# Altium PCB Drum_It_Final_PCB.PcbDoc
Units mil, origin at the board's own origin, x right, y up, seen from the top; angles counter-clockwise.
Board outline 6000 x 4000 mil, 2 copper layers (Top Layer, Bottom Layer); 23 components, 16 nets, 73 pads, 2 vias.
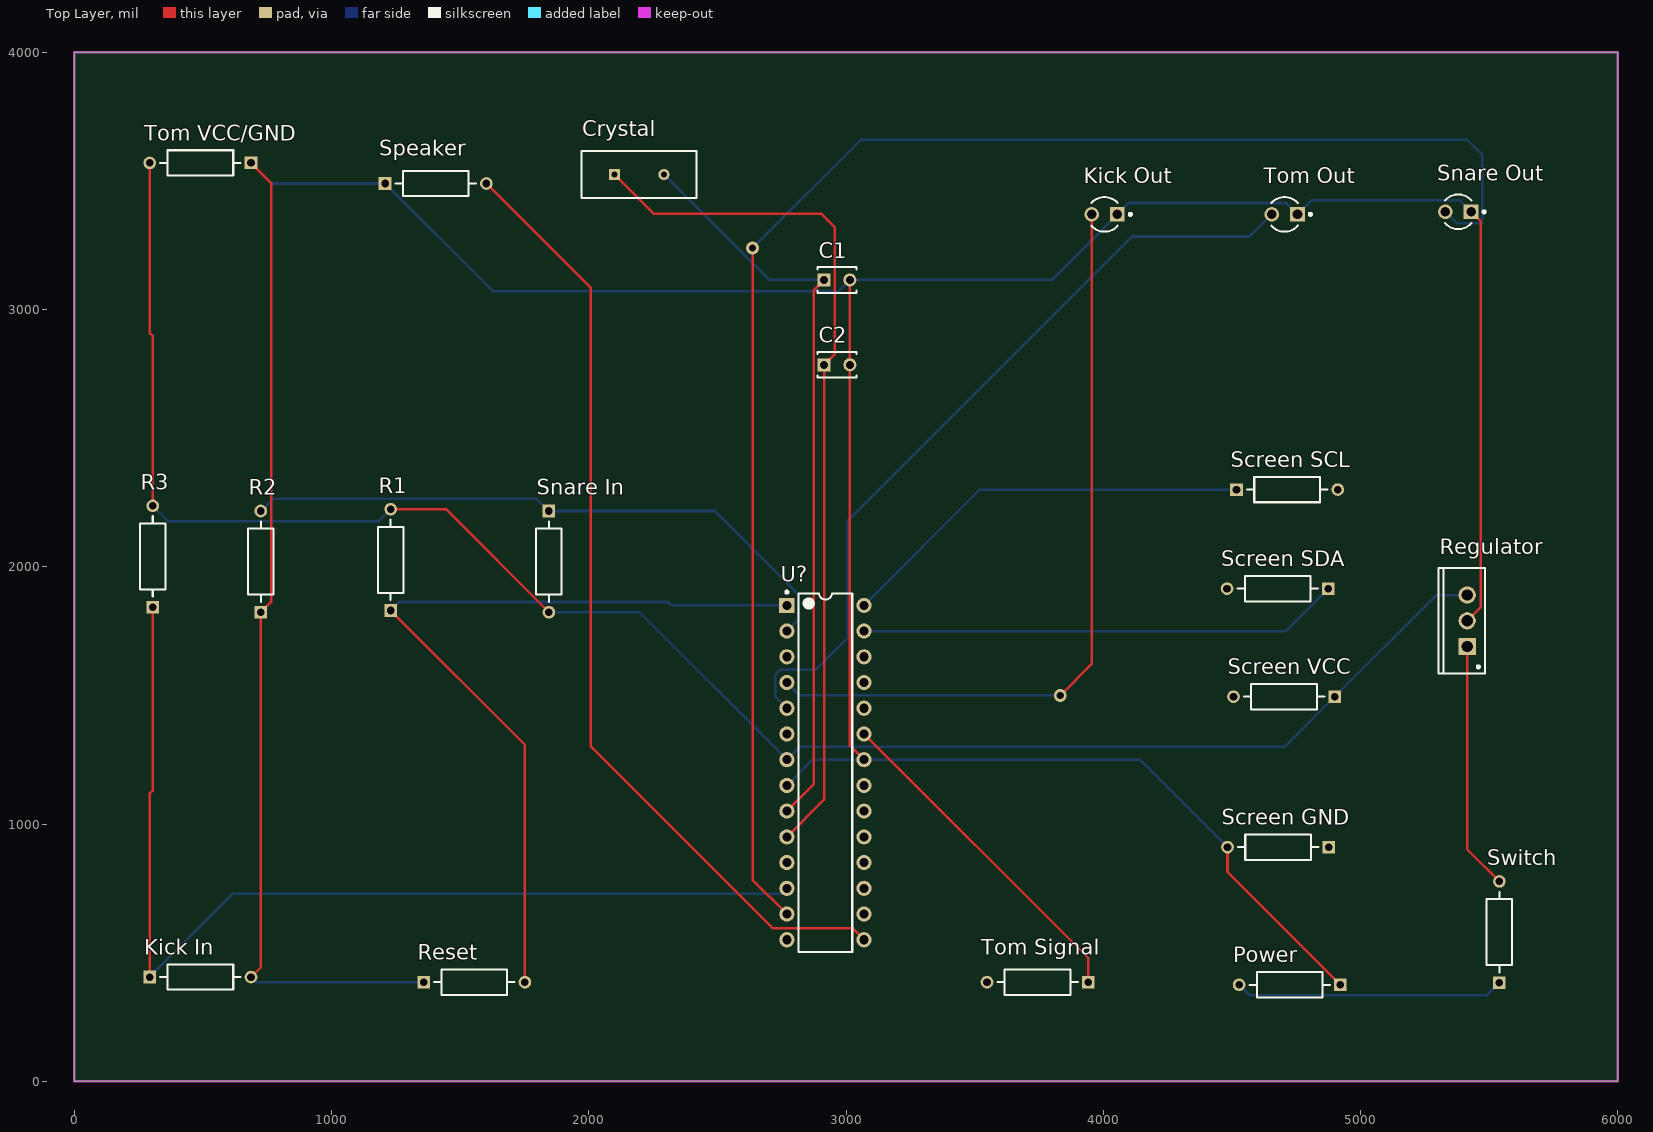
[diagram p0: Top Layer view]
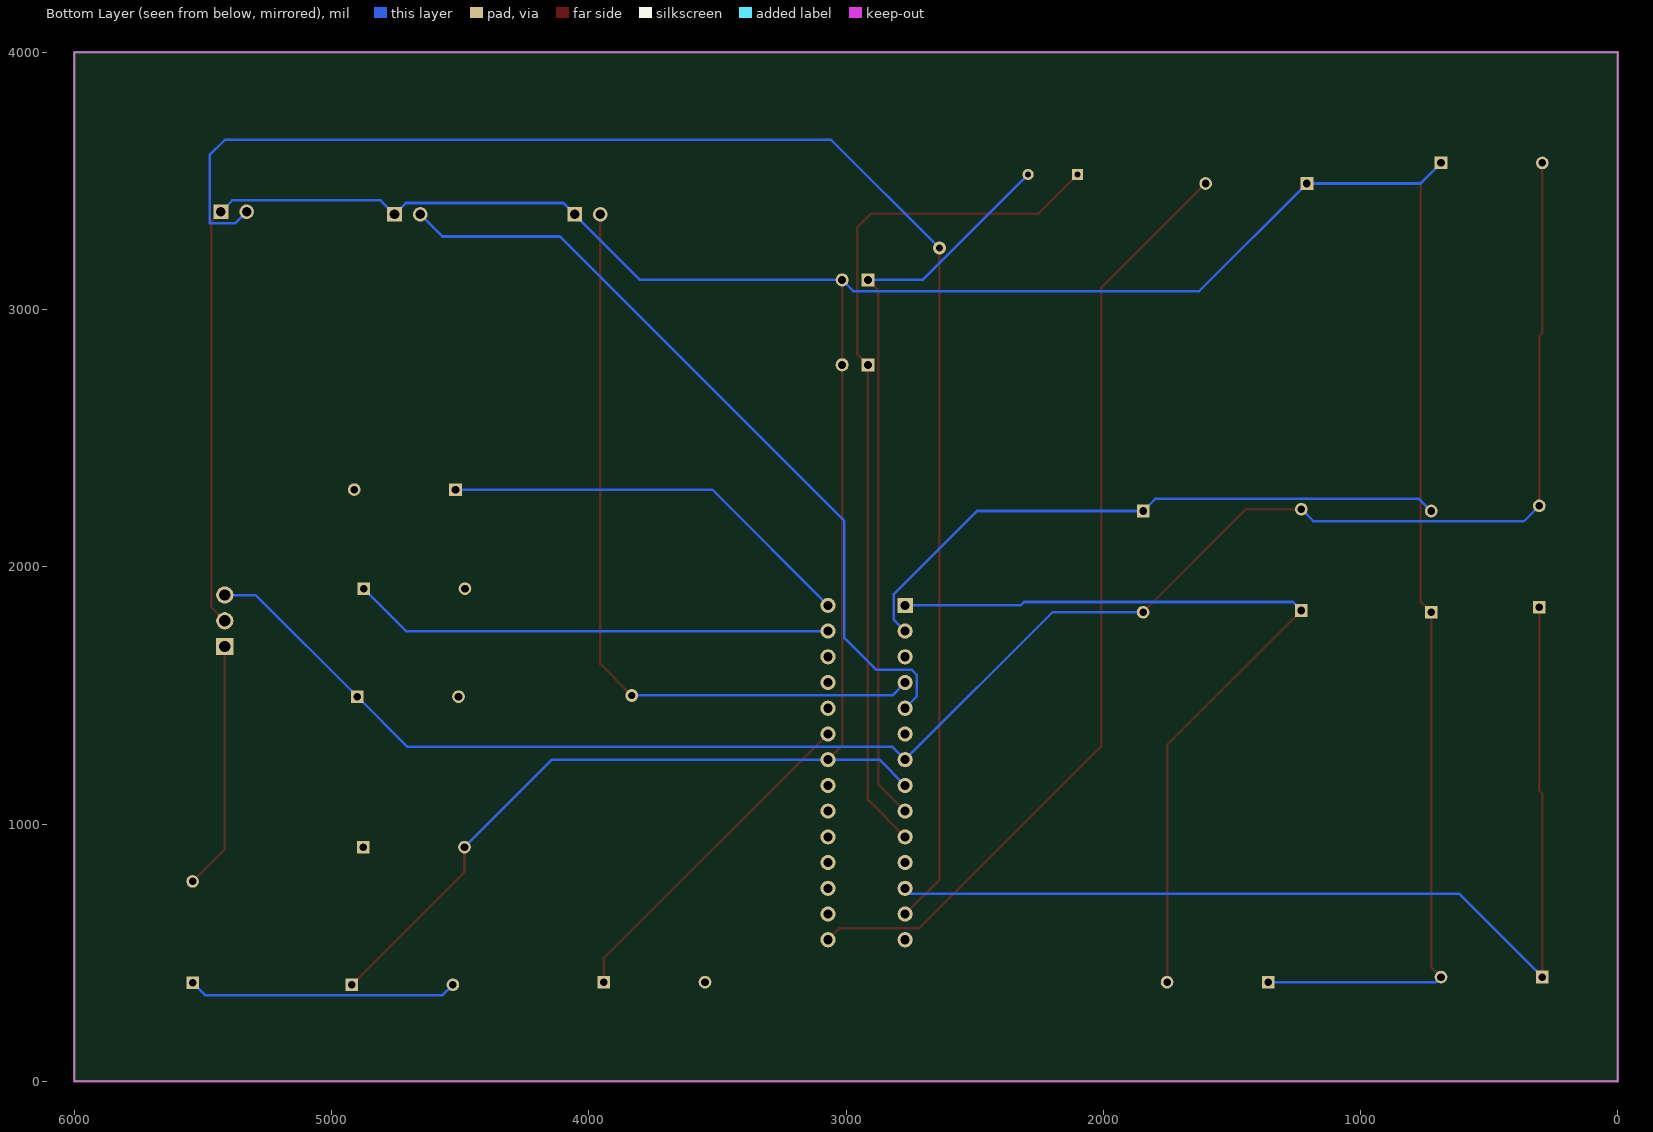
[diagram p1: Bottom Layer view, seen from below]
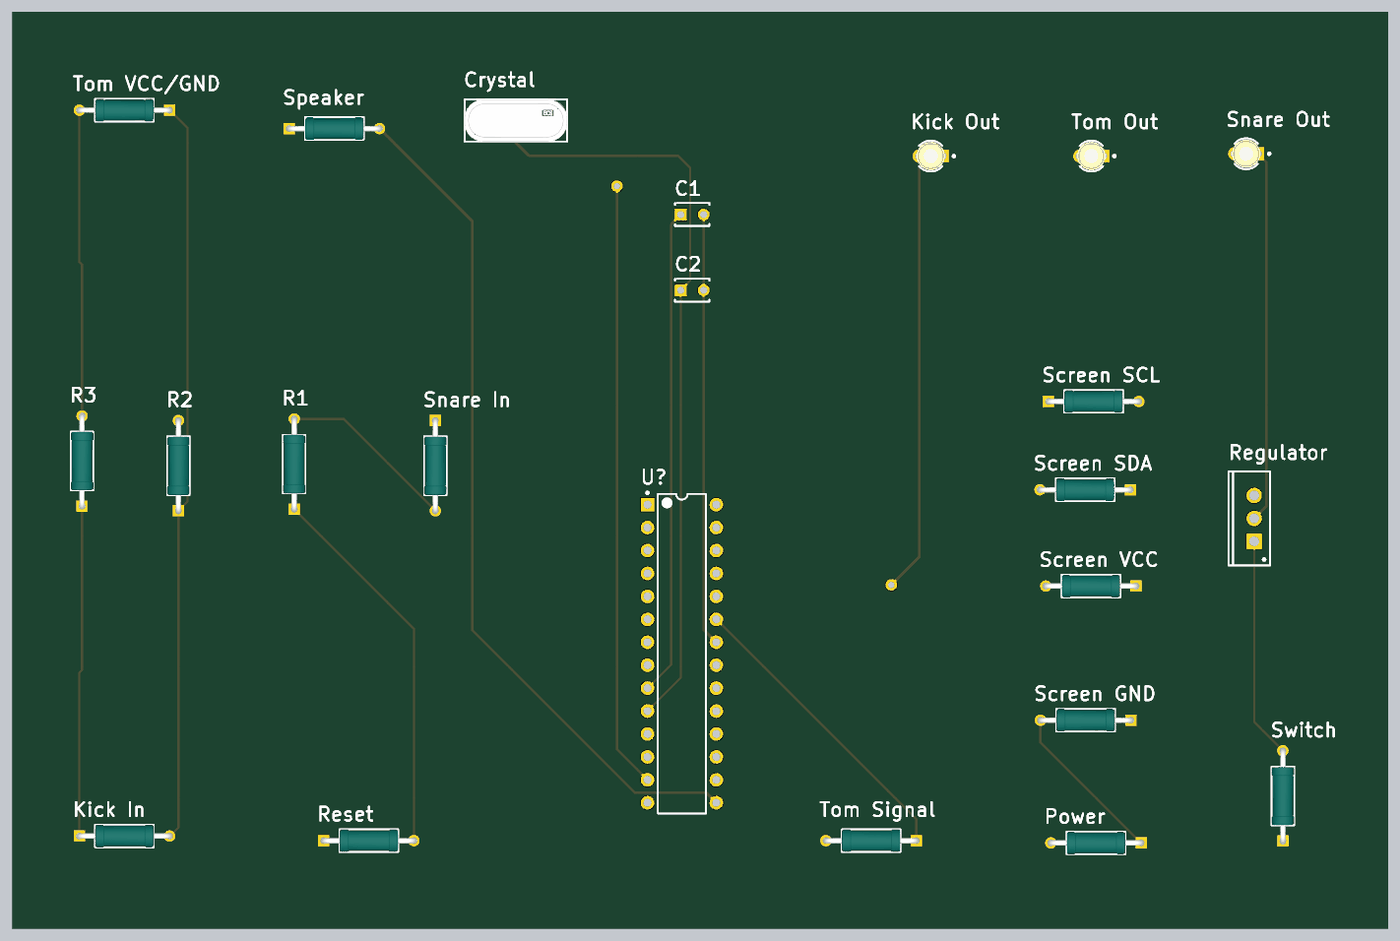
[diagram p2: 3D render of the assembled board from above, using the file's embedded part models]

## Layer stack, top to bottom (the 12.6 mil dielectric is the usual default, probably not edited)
Top Solder: solder mask 0.4, Solder Resist, Dk 3.5
Top Layer: signal copper 1.4
Dielectric 1: dielectric 12.6, FR-4, Dk 4.8
Bottom Layer: signal copper 1.4
Bottom Solder: solder mask 0.4, Solder Resist, Dk 3.5

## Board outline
0,0 6000,0 6000,4000 0,4000

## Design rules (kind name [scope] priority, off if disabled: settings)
Clearance [All] p1: gap=10 ignorepadtopadclearanceinfootprint=FALSE except(0: Arc-Hole Track-Hole SMDPad-Hole THPad-Hole Via-Hole Fill-Hole Poly-Hole Region-Hole Text-Hole)
PolygonConnect [All] p1: connectstyle=Relief reliefconductorwidth=10 reliefentries=4 polygonreliefangle="90 Angle" airgapwidth=10
RoutingVias [All] p1: holewidth=28 width=50 viastyle="Through Hole" minholewidth=28 minwidth=50 maxholewidth=28 maxwidth=50
SolderMaskExpansion [All] p1: expansion=4 istentingtop=FALSE
Width [All] p1: maxlimit=10 minlimit=10 preferedwidth=10
30 further rules are at their usual default settings.

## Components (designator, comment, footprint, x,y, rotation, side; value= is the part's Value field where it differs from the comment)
C1 "C315C220K1G5TA" KEMT-C315-THT-2 2965,3115 r0 top
C2 "C315C220K1G5TA" KEMT-C315-THT-2 2965,2785 r0 top
Crystal "ECS-80-20-4X" FP-ECS-80-20-4X-MFG 2196.06,3525 r0 top
"Kick In" "MRS25000C1000FRP00" FP-MRS25-MFG 490,405 r0 top
"Kick Out" "HLMP-1719" FP-HLMP-1719-MFG 4005,3370 r180 top
Power "MRS25000C1000FRP00" FP-MRS25-MFG 4725,375 r180 top
R1 "MRS25000C1000FRP00" FP-MRS25-MFG 1230,2026.85 r90 top
R2 "MRS25000C1000FRP00" FP-MRS25-MFG 725,2020 r90 top
R3 "MRS25000C1000FRP00" FP-MRS25-MFG 305,2040 r90 top
Regulator "L7805CV" TO220 5415,1790 r90 top
Reset "MRS25000C1000FRP00" FP-MRS25-MFG 1555,385 r0 top
"Screen GND" "MRS25000C1000FRP00" FP-MRS25-MFG 4680,910 r180 top
"Screen SCL" "MRS25000C1000FRP00" FP-MRS25-MFG 4715,2300 r0 top
"Screen SDA" "MRS25000C1000FRP00" FP-MRS25-MFG 4678.15,1915 r180 top
"Screen VCC" "MRS25000C1000FRP00" FP-MRS25-MFG 4703.15,1495 r180 top
"Snare In" "MRS25000C1000FRP00" FP-MRS25-MFG 1845,2020 r270 top
"Snare Out" "HLMP-1719" FP-HLMP-1719-MFG 5380,3380 r180 top
Speaker "MRS25000C1000FRP00" FP-MRS25-MFG 1405,3490 r0 top
Switch "MRS25000C1000FRP00" FP-MRS25-MFG 5540,580 r90 top
"Tom Out" "HLMP-1719" FP-HLMP-1719-MFG 4705,3370 r180 top
"Tom Signal" "MRS25000C1000FRP00" FP-MRS25-MFG 3745,385 r180 top
"Tom VCC/GND" "MRS25000C1000FRP00" FP-MRS25-MFG 490,3570 r180 top
U? "ATmega328-PU" 28P3 2920,1200 r0 top

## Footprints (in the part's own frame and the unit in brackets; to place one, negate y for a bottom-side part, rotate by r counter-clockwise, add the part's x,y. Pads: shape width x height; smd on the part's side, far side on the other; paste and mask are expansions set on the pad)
28P3 [mm] "28-Pin Plastic Dual In-Line Package (PDIP)"
  rect 1.5x1.5 hole 0.9: 1(-3.81,16.51)
  round 1.5 hole 0.9: 2(-3.81,13.97) 3(-3.81,11.43) 4(-3.81,8.89) 5(-3.81,6.35) 6(-3.81,3.81) 7(-3.81,1.27) 8(-3.81,-1.27) 9(-3.81,-3.81) 10(-3.81,-6.35) 11(-3.81,-8.89) 12(-3.81,-11.43) 13(-3.81,-13.97) 14(-3.81,-16.51) 15(3.81,-16.51) 16(3.81,-13.97) 17(3.81,-11.43) 18(3.81,-8.89) 19(3.81,-6.35) 20(3.81,-3.81) 21(3.81,-1.27) 22(3.81,1.27) 23(3.81,3.81) 24(3.81,6.35) 25(3.81,8.89) 26(3.81,11.43) 27(3.81,13.97) 28(3.81,16.51)
  silkscreen extent -3.93,-17.7 2.65,17.93, body extent -3.6,-17.65 3.6,17.65, height 4.58
FP-ECS-80-20-4X-MFG [mm]
  rect 1.1x1.1 hole 0.6 paste-1000 mask+0: 1(-2.44,0)
  round 1.1 hole 0.6 paste-1000 mask+0: 2(2.44,0)
  silkscreen extent -5.68,-2.33 5.68,2.33, body extent -5.77,-2.42 5.77,2.42, height 0.25
FP-HLMP-1719-MFG [mm]
  rect 1.45x1.45 hole 0.95 paste-1000 mask+0: 1(-1.27,0)
  round 1.45 hole 0.95 paste-1000 mask+0: 2(1.27,0)
  silkscreen extent -2.68,-1.71 1.3,1.71, body extent -2.22,-2.22 2.22,2.22, height 0.25
FP-MRS25-MFG [mm]
  rect 1.25x1.25 hole 0.75 paste-1000 mask+0: 1(-5,0)
  round 1.25 hole 0.75 paste-1000 mask+0: 2(5,0)
  silkscreen extent -3.97,-1.25 3.97,1.25, body extent -5.72,-1.35 5.72,1.35, height 0.25
KEMT-C315-THT-2 [mm] "THD, 2-Leads, Body 3.81x2.54mm"
  rect 1.3x1.3 hole 0.8: 1(-1.27,0)
  round 1.3 hole 0.8: 2(1.27,0)
  silkscreen extent -1.91,-1.27 1.91,1.27, body extent -1.91,-1.27 1.91,1.27, height 4.66
TO220 [mm] "TO, Thru-Hole, Vertical, Heatsink Mounted; 3 In-Line Leads; Pitch 2.54 mm"
  rect 1.7x1.7 hole 1.1: 1(-2.54,0)
  round 1.7 hole 1.1: 2(0,0) 3(2.54,0)
  silkscreen extent -5.2,-1.75 5.2,2.85, body extent -5.25,-1.8 5.25,2.9, height 19.7

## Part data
C1 C2: library part CMP-1664-00008-1, "Capacitor, Ceramic, 22 pF, +/-10 %, 100 V, -55 to 125 degC, 2-Pin THD, RoHS, Bulk", Case\Package=TO-220, Max Input Voltage="40 V", Max Operating Temperature="125 degC", Max Ouput Current="1.5 A", Min Input Voltage="4.2 V", Min Operating Temperature="0 degC", Output Voltage="1.2 V", Package Quantity=50
Crystal: library part CMP-1669-00002-3, ESR (Equivalent Series Resistance)=80Ω, Frequency=8MHz, Frequency Stability=50ppm, Frequency Tolerance=0.003%, Load Capacitance=20pF, Max Operating Temperature=70°C, Min Operating Temperature=-10°C
"Kick In" Power R1 R2 R3 Reset "Screen GND" "Screen SCL" "Screen SDA" "Screen VCC" "Snare In" Speaker Switch "Tom Signal" "Tom VCC/GND": library part CMP-00030-42757237-1, "MRS25000C1000FRP00 Resistor, 100 Ohm, ± 1%, 600 mW, Axial Leaded, Metal Film (Thin Film), Professional", Case/Package=Axial, Max Operating Temperature=155°C, Max Power Dissipation=600mW, Min Operating Temperature=-55°C, Resistance=100Ω, Temperature Coefficient=50ppm/°C, Tolerance=1%, Voltage Rating=350V
"Kick Out" "Snare Out" "Tom Out": library part CMP-2000-06410-2, "LED YELLOW DIFFUSED T-1 T/H", Colour=Yellow, Forward Current=2mA, Forward Voltage=1.8V, Manufacturer=Broadcom, Package=0, Power Dissipation=17.5mW, Reverse Voltage=5V, Temperature="-40°C to +100°C", Temperature Range High=+100°C, Temperature Range Low=-40°C
Regulator: library part CMP-0244-00483-1, "Positive Voltage Regulator, 5V, 3-Pin TO-220"
U?: library part CMP-0095-00015-2, "8-bit AVR Microcontroller, 32KB Flash, 1KB EEPROM, 2KB SRAM, 28-pin PDIP, Industrial Grade (-40°C to 85°C)"

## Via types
v1: diameter 50, hole 28, Top Layer to Bottom Layer, 2 vias

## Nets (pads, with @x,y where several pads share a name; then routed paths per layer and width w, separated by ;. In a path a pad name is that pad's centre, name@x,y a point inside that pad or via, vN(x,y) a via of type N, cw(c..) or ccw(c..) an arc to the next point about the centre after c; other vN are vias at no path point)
NetC1_1: C1.1 Crystal.2 U?.9 | length 2917.8
  Top Layer w10: U?.9 2874,1154 2874,3074 C1.1
  Bottom Layer w10: Crystal.2 2702.13,3115 C1.1
NetC1_2: "Kick In.2" "Kick Out.1" "Screen GND.2" "Snare Out.1" "Tom Out.1" "Tom VCC/GND.1" C1.2 C2.2 Power.1 R2.1 Regulator.2 Reset.1 Speaker.1 U?.8 U?.22 | length 15187.7
  Top Layer w10: 686.85,405 725,443.15 R2.1 765,1863.15 765,3491.85 686.85,3570 ; C1.2 C2.2 3015,1305 U?.22 ; 4483.15,910 4483.15,813.7 Power.1 ; Regulator.2 5468,1843 5468,3342 5430,3380
  Bottom Layer w10: 686.85,405 706.85,385 Reset.1 ; 686.85,3570 766.85,3490 Speaker.1 1627.15,3071 2971,3071 C1.2 3800,3115 4055,3370 4099,3414 4711,3414 4755,3370 4809,3424 5386,3424 5430,3380 ; U?.8 2870,1250 U?.22 4143.15,1250 4483.15,910
NetC2_1: C2.1 Crystal.1 U?.10 | length 3388
  Top Layer w10: Crystal.1 2253,3372 2904,3372 2956,3320 2956,2826 C2.1 2915,1095 U?.10
"NetKick In_1": "Kick In.1" R3.1 U?.12 | length 4062.8
  Top Layer w10: 293.15,405 293.15,1118 305,1129.85 R3.1
  Bottom Layer w10: 293.15,405 617.15,729 2749,729 U?.12
"NetKick Out_2": "Kick Out.2" U?.4 | length 3004.2
  Top Layer w10: v1(3833,1500) 3955,1622 3955,3370
  Bottom Layer w10: U?.4 2820,1500 v1(3833,1500)
NetPower_2: Power.2 Switch.1 | length 1048.4
  Bottom Layer w10: Power.2 4568.15,335 5491.85,335 Switch.1
NetR1_1: R1.1 Reset.2 U?.1 | length 3220.2
  Top Layer w10: R1.1 1751.85,1308.15 Reset.2
  Bottom Layer w10: R1.1 1263,1863 2308,1863 2321,1850 U?.1
NetR1_2: "Screen VCC.1" "Snare In.2" "Tom VCC/GND.2" R1.2 R3.2 Regulator.3 U?.7 | length 7160.6
  Top Layer w10: 293.15,3570 293.15,2908.85 305,2897 R3.2 ; R1.2 1444.45,2223.7 1845,1823.15
  Bottom Layer w10: R3.2 364.85,2177 1183.3,2177 R1.2 ; 1845,1823.15 2196.85,1823.15 U?.7 2820,1300 4705,1300 4900,1495 5295,1890 Regulator.3
NetR2_2: "Snare In.1" R2.2 U?.2 | length 2424.3
  Bottom Layer w10: R2.2 772.15,2264 1797.85,2264 1845,2216.85 2490.15,2216.85 2815,1892 2815,1795 U?.2
NetRegulator_1: Regulator.1 Switch.2 | length 964.9
  Top Layer w10: Regulator.1 5415,901.85 Switch.2
"NetScreen SCL_1": "Screen SCL.1" U?.28 | length 1634.5
  Bottom Layer w10: U?.28 3520,2300 4518.15,2300
"NetScreen SDA_1": "Screen SDA.1" U?.27 | length 1873.3
  Bottom Layer w10: U?.27 4710,1750 4875,1915
"NetSnare Out_2": "Snare Out.2" U?.13 | length 6106.6
  Top Layer w10: v1(2637,3239) 2637,783 U?.13
  Bottom Layer w10: v1(2637,3239) 3058,3660 5414,3660 5474,3600 5474,3336 5374,3336 5330,3380
NetSpeaker_2: Speaker.2 U?.15 | length 3729.7
  Top Layer w10: Speaker.2 2007,3084.85 2007,1303 2715,595 3025,595 U?.15
"NetTom Out_2": "Tom Out.2" U?.5 | length 3086.6
  Bottom Layer w10: U?.5 2725,1495 2725,1580 2745,1600 2883,1600 3006,1723 3006,2178 4112,3284 4569,3284 4655,3370
"NetTom Signal_1": "Tom Signal.1" U?.23 | length 1326.1
  Top Layer w10: U?.23 3941.85,478.15 3941.85,385
pads on no net: "Screen GND.1" "Screen SCL.2" "Screen SDA.2" "Screen VCC.2" "Tom Signal.2" U?.3 U?.6 U?.11 U?.14 U?.16 U?.17 U?.18 U?.19 U?.20 U?.21 U?.24 U?.25 U?.26

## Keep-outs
Keep-Out Layer:
  the board outline again, w10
